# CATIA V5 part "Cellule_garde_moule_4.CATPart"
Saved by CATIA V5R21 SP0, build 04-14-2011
Part number: Moule_cellule_garde
Bounding box of the stored display mesh (mm): x -18 to 18, y -75 to 75, z -17 to 0
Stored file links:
  C:\Users\zerma\Pictures\Moule_3\Cellule_garde_moule_4.CATPart
  Product1.CATProduct
  C:\Users\zerma\Pictures\Moule\Moule_v1.CATPart
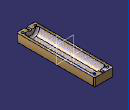
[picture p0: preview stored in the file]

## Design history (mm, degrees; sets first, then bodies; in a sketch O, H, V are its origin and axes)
Body1 (main body)
  Sketch1 on yz-plane, origin (0, 0, 0), H (0, 1, 0), V (0, 0, 1)
    line L1 (-95, -12.5) -> (95, -12.5)
    point P1 (-95, -12.5)
    line L2 (-100, -15) -> (100, -15)
    point P3 (-100, -15)
    line L3 (-95, -12.5) -> (-95, 0)
    point P5 (-95, 0)
    line L4 (-100, -15) -> (-100, 0)
    point P6 (-100, 0)
    line L5 (-95, 0) -> (-100, 0)
    point P7 (100, 0)
    point P8 (100, -15)
    line L6 (100, -15) -> (100, 0)
    point P9 (95, 0)
    line L7 (95, 0) -> (100, 0)
    point P10 (95, -12.5)
    line L8 (95, -12.5) -> (95, 0)
    distance L1 H = 12.5
    distance L1 L2 = 2.5
    length L4 = 15
    distance L4 L3 = 5
    length L1 = 190
    length L2 = 200
    distance V L3 = 95
    horizontal: L1 H, L2 H, L5 H
    vertical: L3 V, L4 V
    symmetry: P6 P7 V, P3 P8 V, L4 L6 V, P5 P9 V, L5 L7 V, P1 P10 V, L3 L8 V
  Shaft1: profile Sketch1, axis Sketch1.H, angle 360
  Sketch2 on face of Shaft1 from Sketch1.L4, origin (0, -100, 0), H (1, 0, 0), V (0, 0, 1)
    line L1 (-10, 2.5) -> (10, 2.5)
    line L2 (10, 2.5) -> (10, -2.5)
    line L3 (10, -2.5) -> (-10, -2.5)
    line L4 (-10, -2.5) -> (-10, 2.5)
    length L2 = 5
    length L1 = 20
    horizontal: L1 H, L3 H
    vertical: L2 V, L4 V
    symmetry: L3 L1 H, L4 L2 V
  Pad1: profile Sketch2, direction (0, -1, 0), length 15
  Sketch3 on face of Pad1 from Sketch2.L1, origin (0, 0, 2.5), H (1, 0, 0), V (0, 1, 0)
    circle A1 centre (0, -107.5) radius 2.5
    point P1 (0, -107.5)
    reference intersected line E1 (14.7902, -100) -> (-14.7902, -100) from face of Shaft1 from Sketch1.L4
    radius A1 = 2.5
    distance P1 E1 = 7.5
    coincidence: P1 V
  Pocket1: profile Sketch3, direction (0, 0, -1), length 5, mirrored extent
  Fillet1: radius 2, on edge [face of Pad1 from Sketch2.L4 | end face of Pad1]; edge [face of Pad1 from Sketch2.L1 | end face of Pad1]; edge [face of Pad1 from Sketch2.L3 | end face of Pad1]; edge [face of Pad1 from Sketch2.L2 | end face of Pad1]; edge [face of Pad1 from Sketch2.L2 | face of Pad1 from Sketch2.L3]; edge [face of Shaft1 from Sketch1.L4 | face of Pad1 from Sketch2.L3]; edge [face of Pad1 from Sketch2.L3 | face of Pad1 from Sketch2.L4]; edge [face of Pocket1 from Sketch3.A1 | face of Pad1 from Sketch2.L3]; edge [face of Pad1 from Sketch2.L4 | face of Pad1 from Sketch2.L1]; edge [face of Pad1 from Sketch2.L1 | face of Pad1 from Sketch2.L2]; edge [face of Shaft1 from Sketch1.L4 | face of Pad1 from Sketch2.L1]; edge [face of Shaft1 from Sketch1.L4 | face of Pad1 from Sketch2.L4]; edge [face of Shaft1 from Sketch1.L4 | face of Pad1 from Sketch2.L2]; face of Pad1 from Sketch2.L1
  Mirror1: of Pad1, Pocket1, Fillet1, about zx-plane
  Fillet2: radius 4, on edge [face of Shaft1 from Sketch1.L2 | face of Shaft1 from Sketch1.L6]; edge [face of Shaft1 from Sketch1.L4 | face of Shaft1 from Sketch1.L2]
Body2
  Sketch4 on xy-plane, origin (0, 0, 0), H (1, 0, 0), V (0, 1, 0)
    line L1 (18, 75) -> (18, -75)
    line L2 (18, -75) -> (-18, -75)
    line L3 (-18, -75) -> (-18, 75)
    line L4 (-18, 75) -> (18, 75)
    length L1 = 150
    length L4 = 36
    vertical: L1 V, L3 V
    horizontal: L2 H, L4 H
    equidistance: L1 L3 O, L2 L4 O
  Pad2: profile Sketch4, direction (0, 0, -1), length 17
  Body3
    Sketch5 on yz-plane, origin (0, 0, 0), H (0, 1, 0), V (0, 0, 1)
      line L1 (-61, -5.5) -> (61, -5.5)
      point P1 (-61, -5.5)
      point P2 (61, -5.5)
      line L2 (-66, -13.5) -> (66, -13.5)
      point P3 (-66, -13.5)
      point P4 (66, -13.5)
      line L3 (-61, -5.5) -> (-61, 0)
      point P5 (-61, 0)
      line L4 (-66, -13.5) -> (-66, -2.5)
      point P6 (-66, -2.5)
      point P7 (66, -2.5)
      point P8 (66, -13.5)
      line L5 (66, -13.5) -> (66, -2.5)
      point P9 (61, 0)
      point P10 (61, -5.5)
      line L6 (61, -5.5) -> (61, 0)
      line L7 (-66, -2.5) -> (-78, -2.5)
      line L8 (-78, -2.5) -> (-78, 0)
      line L9 (-78, 0) -> (-61, 0)
      point P13 (-61, 0)
      line L10 (66, -2.5) -> (73, -2.5)
      line L11 (73, -2.5) -> (73, 0)
      line L12 (73, 0) -> (61, 0)
      distance L1 H = 5.5
      distance L1 L2 = 8
      distance L4 L3 = 5
      distance V L3 = 61
      length L9 = 17
      length L12 = 12
      length L11 = 2.5
      horizontal: L1 H, L2 H, L7 H, L9 H, L10 H, L12 H
      vertical: L3 V, L4 V, L8 V, L11 V
      symmetry: P6 P7 V, P3 P8 V, L4 L5 V, P5 P9 V, P1 P10 V, L3 L6 V
      coincidence: P13 P5, L9 H, P4 P8, P2 P10
    Shaft2: profile Sketch5, axis Sketch5.H, angle 360
  Remove1: tool Body3
  Sketch6 on face of Shaft2 from Sketch5.L6, origin (0, 61, 0), H (-1, 0, 0), V (0, 0, 1)
    circle A1 centre (0, 0) radius 5.5
    reference projected circle E1 centre (0, 0) radius 5.5 from edge [face of Shaft2 from Sketch5.L1 | face of Shaft2 from Sketch5.L6]
    reference projected circle E2 centre (0, 0) radius 5.5 from edge [face of Shaft2 from Sketch5.L1 | face of Shaft2 from Sketch5.L6]
    coincidence: A1 E1
    concentricity: A1 E2
  Pocket2: profile Sketch6, direction (0, -1, 0), up to face of Shaft2 from Sketch5.L3
  Sketch7 on end face of Pad2, origin (0, 0, -17), H (1, 0, 0), V (0, -1, 0)
    circle A1 centre (12, 69) radius 2.25
    point P1 (12, 69)
    circle A2 centre (12, -69) radius 2.25
    circle A3 centre (-12, 69) radius 2.25
    circle A4 centre (-12, -69) radius 2.25
    reference projected line E1 (18, 75) -> (18, -75) from edge [end face of Pad2 | face of Pad2 from Sketch4.L1]
    reference projected line E2 (-18, 75) -> (18, 75) from edge [end face of Pad2 | face of Pad2 from Sketch4.L2]
    radius A1 = 2.25
    distance P1 E1 = 6
    distance P1 E2 = 6
    symmetry: A1 A2 H, A1 A3 V, A3 A4 H
  Pocket3: profile Sketch7, direction (0, 0, 1), length 50, mirrored extent
  Chamfer1: length 2, angle 45, on edge [face of Pad2 from Sketch4.L4 | face of Pad2 from Sketch4.L3]; edge [end face of Pad2 | face of Pad2 from Sketch4.L4]; edge [end face of Pad2 | face of Pad2 from Sketch4.L3]; edge [face of Pad2 from Sketch4.L1 | face of Pad2 from Sketch4.L4]; edge [end face of Pad2 | face of Pad2 from Sketch4.L1]; edge [end face of Pad2 | face of Pad2 from Sketch4.L2]; edge [face of Pad2 from Sketch4.L2 | face of Pad2 from Sketch4.L1]; edge [face of Pad2 from Sketch4.L3 | face of Pad2 from Sketch4.L2]
  Fillet3: radius 4, on edge [face of Shaft2 from Sketch5.L5 | face of Shaft2 from Sketch5.L2]
  Fillet4: radius 4, on edge [face of Shaft2 from Sketch5.L2 | face of Shaft2 from Sketch5.L4]
  CLDGeom1 "Maillage.1"
  CLDGeom2 "Maillage.2"
  CLDGeom3 "Maillage.3"
  CLDGeom4 "Maillage.4"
